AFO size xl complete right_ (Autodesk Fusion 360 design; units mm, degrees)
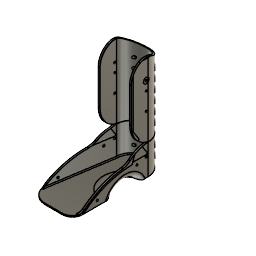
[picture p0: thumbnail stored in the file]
part number: 2025-10-02-12-56-12-317
parameter "d73" = 49
parameter "d131" = 16
sketch "Sketch1" plane through (0, 0, 0) normal (0, 0, 1) x axis (1, 0, 0)
  line L1 (28, -127.4) -> (-48, -127.4)
  line L2 (28, 0) -> (28, -127.4)
  line L3 (25, 0) -> (25, -127.4)
  line L4 (28, 0) -> (25, 0)
  line L5 (-18.603, -127.4) -> (-18.603, -115.6)
  line L6 (10.5, -127.4) -> (10.5, -109.9)
  line L7 (10.5, -127.4) -> (-18.603, -127.4)
  line L8 (36.7314, -101.9) -> (-43.9969, -101.9)
  line L9 (0, 0) -> (-28.984, 0)
  line L10 (-45, -127.4) -> (-25, 0)
  line L11 (-40.9969, -101.9) -> (-44.0794, -101.4161)
  line L12 (-48, -127.4) -> (-28, 0)
  line L13 (-43.6846, -101.9) -> (-43.6828, -102.2021)
  circle C1 centre (0, 0) radius 28
  circle C2 centre (0, 0) radius 25
  circle C3 centre (10.5, -109.9) radius 17.5
  circle C4 centre (-18.1846, -101.9) radius 22.5
  circle C5 centre (10.5, -109.9) radius 14.5
  circle C6 centre (-18.1846, -101.9) radius 25.5
  point P1 (0, 0)
  point P2 (0, 0)
  point P5 (28, 0)
  point P6 (0, 0)
  point P7 (25, 0)
  point P8 (25, -127.4)
  point P13 (-18.603, -127.4)
  point P11 (10.5, -109.9)
  point P14 (10.5, -109.9)
  point P15 (10.5, -127.4)
  point P20 (-25, 0)
  point P21 (-45, -127.4)
  point P22 (-40.9969, -101.9)
  point P10 (-18.1846, -101.9)
  point P25 (-28, 0)
  point P16 (-43.9969, -101.9)
  point P26 (-43.6828, -102.2021)
  point P27 (-43.6846, -101.9)
  point P19 (0, 0)
  coincident P1 P2
  coincident C1 P5
  tangent C1 L2
  perpendicular L1 L2
  coincident P1 P6
  vertical L3
  coincident C2 P7
  perpendicular L2 L4
  coincident L1 P8
  tangent L2 C3
  tangent L1 C3
  concentric C3 C5
  tangent L3 C5
  coincident L1 P13
  perpendicular L1 L5
  coincident P11 P14
  coincident L1 P15
  coincident C3 P15
  perpendicular L1 L6
  perpendicular L5 L8
  horizontal L9
  coincident C2 P20
  coincident L9 P20
  coincident L1 P21
  coincident L10 P22
  coincident L8 P22
  parallel L2 L3
  coincident P10 L8
  concentric C4 C6
  coincident L9 P25
  coincident C1 P25
  parallel L10 L12
  coincident P16 L12
  coincident C6 P26
  coincident L8 P27
  coincident C6 P27
  coincident P1 P19
  tangent L1 C6
  tangent C6 L12
  perpendicular L11 L12
  dimension "d2" diameter C1 = 56 (= "d57 + ( 3 * 2 ) * 1 mm")
  dimension "d4" distance P2 L1 = 127.4 (= "152.4 mm - 25 mm")
  dimension "d57" diameter C2 = 50
  dimension "d74" diameter C3 = 35
  dimension "d252" diameter C4 = 45 (= "d73 - 4 mm")
  dimension "d322" distance P8 P21 = 70
  dimension "d323" diameter C6 = 51 (= "d252 + 6 mm")
extrude "Extrude1" new body sketch "Sketch1" profile of C1 L2 L3 L4 C3 L8 L9 L10 L11 C6 L12 along normal blind 35
extrude "Extrude2" add sketch "Sketch1" profile of C1 L1 L2 C2 L3 C3 C4 C5 L5 L6 L7 L8 L10 L11 C6 L13 along normal blind 3
extrude "Extrude15" new body sketch "Sketch1" profile of C1 C2 L4 L9 along normal blind 178
combine "Combine2"
work_plane "WorkPlane1" RotateAngle -90
fillet "Fillet69" radius 1 1
sketch "Sketch23" plane through (28, 0, 0) normal (1, 0, 0) x axis (0, 1, 0)
  line L1 (-28, 78) -> (0, 35)
  line L2 (-28, 178) -> (-28, 78)
  line L3 (0, 178) -> (-28, 178)
  line L4 (0, 35) -> (0, 178)
  circle C1 centre (-3, 143) radius 1.75
  point P5 (0, 178)
  point P6 (0, 178)
  point P2 (0, 35)
  point P8 (0, 35)
  point P4 (-28, 178)
  point P3 (-28, 78)
  point P7 (-3, 143)
  horizontal L3
  perpendicular L3 L4
  coincident P5 P6
  coincident P2 P8
  parallel L2 L4
  dimension "d253" distance P4 P5 = 28
  dimension "d254" distance P3 P4 = 100
  dimension "d255" diameter C1 = 3.5
  dimension "d256" distance L3 P7 = 35
  dimension "d257" distance L2 P7 = 25
extrude "Extrude18" add sketch "Sketch23" against normal blind 3
mirror "Mirror1" mirrorStitchTolerance 0.1
sketch "Sketch24" plane through (0, 16.0046, 10.4216) normal (0, -0.838, -0.5457) x axis (1, 0, 0)
  line L1 (-25, 80.6427) -> (-25, 29.3299)
  line L2 (-28, 80.6427) -> (-25, 80.6427)
  line L3 (-28, 29.3299) -> (-28, 80.6427)
  line L4 (-25, 62.182) -> (-28, 62.182)
  line L5 (-28, 30.2476) -> (-25, 30.2476)
  line L6 (-28, 30.2476) -> (-28, 62.182)
  line L7 (-25, 62.182) -> (-25, 30.2476)
  line L8 (-25, 29.3299) -> (-28, 29.3299)
  point P6 (-28, 62.182)
  point P7 (-25, 62.182)
  point P8 (-25, 30.2476)
  point P9 (-28, 30.2476)
  coincident L3 P6
  coincident L1 P7
  perpendicular L1 L4
  coincident L1 P8
  coincident L3 P9
  perpendicular L3 L5
sketch "Sketch25" plane through (0, 0, 35) normal (0, 0, 1) x axis (-1, 0, 0)
  line L1 (24.843, -1) -> (27.843, -1)
  line L2 (29.5678, 29.0967) -> (24.843, -1)
  line L3 (32.4956, 28.637) -> (29.5678, 29.0967)
  line L4 (32.4956, 28.637) -> (27.843, -1)
  line L5 (0, 0) -> (28.984, 0)
  line L6 (43.3761, 97.9455) -> (28, 0)
  line L7 (25, 0) -> (40.9969, 101.9)
  line L8 (28, 0) -> (25, 0)
  line L9 (40.9969, 101.9) -> (43.6811, 101.4786)
  arc A1 centre (18.1846, 101.9) radius 25.5 clockwise from (43.6811, 101.4786) to (43.3761, 97.9455)
  point P5 (32.4956, 28.637)
  point P4 (29.5678, 29.0967)
  point P15 (28, 0)
  point P8 (25, 0)
  point P2 (27.843, -1)
  horizontal L1
  coincident P5 L6
  coincident P4 L7
  coincident L4 P15
  coincident L2 P8
  perpendicular L3 L4
  dimension "d280" distance P2 P5 = 30
  dimension "d281" distance L1 L5 = 1
loft "Loft1" sketch "Sketch24" + "Sketch25"
sketch "Sketch26" plane through (0, 0, 35) normal (0, 0, 1) x axis (-1, 0, 0)
  line L1 (-28, 0) -> (-28, 101.9)
  line L2 (-25, 0) -> (-28, 0)
  line L3 (-28, -1) -> (-25, -1)
  line L4 (-28, -1) -> (-28, 29)
  line L5 (-25, 29) -> (-28, 29)
  line L6 (-25, -1) -> (-25, 29)
  line L7 (-28, 101.9) -> (-25, 101.9)
  line L8 (-25, 101.9) -> (-25, 0)
  point P5 (-28, -1)
  point P6 (-28, 29)
  point P7 (-25, 29)
  coincident L1 P5
  perpendicular L1 L3
  coincident L1 P6
  coincident P7 L8
  dimension "d278" distance P5 P6 = 30
  dimension "d279" distance L2 L3 = 1
sketch "Sketch27" plane through (0, 16.0046, 10.4216) normal (0, -0.838, -0.5457) x axis (1, 0, 0)
  line L1 (28, 80.6427) -> (28, 29.3299)
  line L2 (25, 80.6427) -> (28, 80.6427)
  line L3 (25, 29.3299) -> (25, 80.6427)
  line L4 (28, 29.3299) -> (25, 29.3299)
  line L5 (28, 63.1164) -> (25, 63.1164)
  line L6 (28, 32.1164) -> (28, 63.1164)
  line L7 (28, 32.1164) -> (25, 32.1164)
  line L8 (25, 63.1164) -> (25, 32.1164)
  point P6 (25, 63.1164)
  point P7 (28, 63.1164)
  point P8 (28, 32.1164)
  point P9 (25, 32.1164)
  coincident L3 P6
  coincident L1 P7
  perpendicular L1 L5
  coincident L1 P8
  coincident L3 P9
  perpendicular L6 L7
  dimension "d282" distance P7 P8 = 31
loft "Loft2" sketch "Sketch27" + "Sketch26"
work_plane "WorkPlane4" AlongDistance 28 (= "25 mm + 3 mm")
sketch "Sketch9" plane through (0, 28, 0) normal (0, 1, 0) x axis (1, 0, 0)
  circle C1 centre (0, -16) radius 2.25
  circle C2 centre (0, -32) radius 2.25
  circle C3 centre (0, -64) radius 2.25
  circle C4 centre (0, -96) radius 2.25
  circle C5 centre (0, -80) radius 2.25
  circle C6 centre (0, -112) radius 2.25
  circle C7 centre (0, -128) radius 2.25
  circle C8 centre (0, -144) radius 2.25
  point P2 (0, -16)
  point P7 (0, 0)
  point P3 (0, -32)
  point P4 (0, -64)
  point P6 (0, -80)
  point P5 (0, -96)
  point P8 (0, -112)
  point P9 (0, -128)
  point P10 (0, -144)
  dimension "d123" diameter C1 = 4.5
  dimension "d124" diameter C2 = 4.5
  dimension "d126" diameter C3 = 4.5
  dimension "d127" diameter C4 = 4.5
  dimension "d128" diameter C5 = 4.5
  dimension "d129" distance P2 P7 = 16
  dimension "d130" distance P2 P3 = 16
  dimension "d133" distance P4 P6 = 16 (= "d131")
  dimension "d134" distance P5 P6 = 16 (= "d131")
  dimension "d291" diameter C6 = 4.5
  dimension "d292" distance P5 P8 = 16 (= "d131")
  dimension "d293" distance P8 P9 = 16 (= "d130")
  dimension "d294" diameter C7 = 4.5
  dimension "d295" diameter C8 = 4.5
  dimension "d296" distance P9 P10 = 16 (= "d131")
extrude "Extrude20" cut sketch "Sketch9" against normal blind 30
path_pattern "PathPattern3" PathPatternDelta 88.0394
fillet "Fillet51" radius 7 15
fillet "Fillet52" radius 130 130
sphere_primitive "SpherePrimitive3" Diameter 55
move_face "MoveFace3"
boundary_fill "BoundaryFill2"
offset_faces "OffsetFaces2" distance 3
shell "Shell7" innerThickness 2.99
fillet "Fillet74" radius 10 15
hole "Hole6" HoleDepth 106.033 HoleDiameter 3.5 TipAngle 118
hole "Hole7" HoleDepth 106.033 HoleDiameter 3.5 TipAngle 118
work_plane "WorkPlane5" AlongDistance 100
work_plane "WorkPlane6" AlongDistance 51.6037
fillet "Fillet76" radius 30
fillet "Fillet79" radius 25
fillet "Fillet83" radius 22
fillet "Fillet85" radius 30 30
fillet "Fillet86" radius 45
split "Split1"
work_plane "WorkPlane7" AlongDistance -28 (= "-( 56 / 2 ) * 1 mm")
sketch "Sketch35" plane through (-28, 0, 0) normal (1, 0, 0) x axis (0, 1, 0)
  circle C1 centre (-2.7874, 31.4508) radius 6
  dimension "d426" diameter C1 = 12
extrude "Extrude22" add sketch "Sketch35" against normal blind 2
fillet "Fillet87" radius 35
sketch "Sketch33" plane through (27.99, 0, 0) normal (1, 0, 0) x axis (0, 1, 0)
  line L1 (0, 139.3302) -> (0, 52.395)
  line L2 (0, 175.01) -> (0, 146.6698)
  line L3 (-11.056, 175.01) -> (0, 175.01)
  line L4 (-25.01, 78.8877) -> (-25.01, 161.056)
  line L5 (-15.1078, 63.6808) -> (-25.01, 78.8877)
  line L6 (-16.1988, 60.7566) -> (-15.1078, 63.6808)
  line L7 (2, 178) -> (28, 178)
  arc A1 centre (7.4005, 86.6037) radius 35 clockwise from (0, 52.395) to (-16.1988, 60.7566)
  arc A2 centre (-3, 143) radius 4.74 clockwise from (0, 139.3302) to (0, 146.6698)
  arc A3 centre (2, 148) radius 30 clockwise from (-25.01, 161.056) to (-11.056, 175.01)
  circle C1 centre (-3, 128) radius 1.5
  circle C2 centre (-3, 98) radius 1.7185
  circle C3 centre (-3, 32) radius 1.75
  point P16 (-3, 128)
  point P17 (-3, 98)
  point P18 (-3, 32)
  vertical P16 P17
  vertical P17 P18
  dimension "d413" diameter C1 = 3
  dimension "d414" distance P16 P17 = 30
  dimension "d415" diameter C3 = 3.5
  dimension "d416" distance P17 P18 = 66
  dimension "d417" distance P16 L7 = 50
  dimension "d418" distance L1 P16 = 3
extrude "Extrude21" cut sketch "Sketch33" profile of C1 C2 C3 against normal blind 133.937
fillet "Fillet88" radius 36
sketch "Sketch37" plane through (-28, 0, 0) normal (1, 0, 0) x axis (0, 1, 0)
fillet "Fillet98" radius 48
fillet "Fillet99" radius 48
sketch "Sketch38" plane through (-28, 0, 0) normal (1, 0, 0) x axis (0, 1, 0)
  line L1 (-5.5406, 132.8689) -> (0, 132.8689)
  line L2 (-5.5406, 93.572) -> (-5.5406, 132.8689)
  line L3 (0, 93.572) -> (-5.5406, 93.572)
  line L4 (0, 132.8689) -> (0, 93.572)
  horizontal L1
  vertical L2
  horizontal L3
  vertical L4
extrude "Extrude24" add sketch "Sketch38" along normal blind 1 and against normal blind 2
fillet "Fillet91" radius 2 2 2 2
fillet "Fillet92" radius 0.5
extrude "Extrude25" cut sketch "Sketch33" profile of C1 C2 against normal blind 188.494
work_plane "WorkPlane8" AlongDistance 178
sketch "Sketch39" plane through (0, 0, 178) normal (0, 0, 1) x axis (1, 0, 0)
  line L1 (-25, 0) -> (25, 0)
  line L2 (30, 0) -> (25, 0)
  line L3 (-32, 0) -> (-25, 0)
  arc A1 centre (0, 10.2) radius 29.8 clockwise from (-28, 0) to (28, 0)
  point P7 (-28, 0)
  horizontal L1
  parallel L1 L2
  parallel L1 L3
  coincident L3 P7
revolve "Revolve2" sketch "Sketch39" AlongAngle -30
fillet "Fillet95" radius 20 20
fillet "Fillet97" radius 1.5
fillet "Fillet100" radius 0.2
